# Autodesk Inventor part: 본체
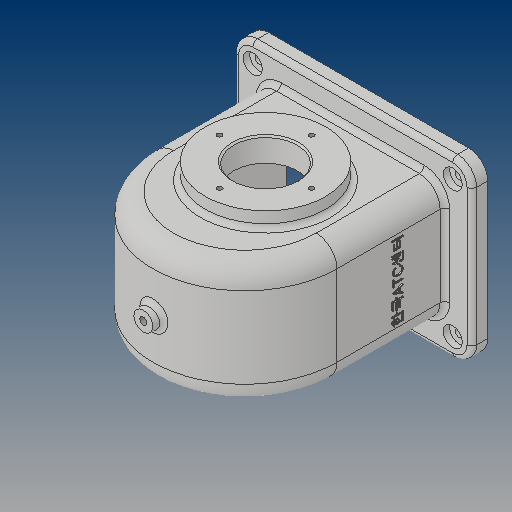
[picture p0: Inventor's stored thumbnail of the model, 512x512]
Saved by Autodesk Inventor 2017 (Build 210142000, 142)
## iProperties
Part Number: 본체
Material: 일반
Document SubType Name: Modeling
Designer: 20
Density: 1 g/cm^3
Appearance: 기본값
Mass: 404.475 g
Surface Area: 1182.21 cm^2
Volume: 404.475 cm^3
Author: 20
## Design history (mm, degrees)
sketch "스케치1"
  geometry: L1 (81.2, 0)-(-81.2, 0) reference; L2 (0, -105.2)-(0, 85.2) reference; L3 (58, -78)-(-58, -78); L4 (58, 0)-(58, -78); L5 (-58, 0)-(-58, -78); A1 r 58 centre (0, 0) between (58, 0) and (-58, 0); 1 further point
  constraints: 6 end point, 2 point on circle, 2 point on line, 2 vertical, 1 centre point, 1 coincident, 1 parallel, 1 tangent
  dimensions: "d0" = 78 distance between parallel lines of L1 L3; "d3" = 116 diameter of A1
extrude "돌출1" new body sketch "스케치1" stored distance "d4" = 77; taper "d5" = 0 deg
sketch "스케치2"
  geometry: L1 (81.2, 0)-(-81.2, 0) reference; L2 (0, -105.2)-(0, 85.2) reference; L3 (52, 0)-(52, -78); L4 (-58, -78)-(58, -78) reference; L5 (-52, 0)-(-52, -78); L6 (-52, -78)-(52, -78); A1 r 52 centre (0, 0) between (52, 0) and (-52, 0); A2 r 58 centre (0, 0) between (58, 0) and (-58, 0) reference; 1 further point
  constraints: 6 end point, 4 point on line, 2 point on circle, 2 vertical, 1 centre point, 1 coincident, 1 horizontal, 1 tangent
  dimensions: "d6" = 6 radial gap between concentric circles of A2 A1
extrude "돌출3" cut sketch "스케치2" stored distance "d14" = 67; taper "d15" = 0 deg
node "작업 평면1"
sketch "스케치3"
  geometry: L1 (-81.2, 0)-(81.2, 0) reference; L2 (0, -53.9)-(0, 53.9) reference; L3 (-75, -55)-(75, -55); L4 (75, -55)-(75, 55); L5 (75, 55)-(-75, 55); L6 (-75, 55)-(-75, -55); L7 (52, -33.5)-(52, 33.5) reference; L8 (52, -33.5)-(-52, -33.5) reference; L9 (-52, -33.5)-(-52, 33.5) reference; L10 (-52, 33.5)-(52, 33.5) reference; 1 further point
  constraints: 8 end point, 2 parallel, 1 horizontal, 1 perpendicular
  dimensions: "d10" = 110 distance of L5.end L3.start; "d11" = 150 distance of L4.end L5.end; "d12" = 75 distance between parallel lines of L2 L6; "d13" = 55 distance between parallel lines of L1 L3
extrude "돌출4" join sketch "스케치3" distance "d16" = 10; taper "d17" = 0 deg
sketch "스케치4"
  geometry: L1 (-105, 0)-(105, 0) reference; L2 (0, -105.2)-(0, 85.2) reference; L3 (-75, -78)-(75, -78) reference; C1 r 38 at (0, -13); 1 further point
  constraints: 1 centre point, 1 point on line
  dimensions: "d18" = 65 distance from line of L3 C1.centre; "d19" = 76 diameter of C1
extrude "돌출5" join sketch "스케치4" distance "d20" = 5; taper "d21" = 0 deg
sketch "스케치5"
  geometry: L1 (-105, 0)-(105, 0) reference; L2 (0, 105.2)-(0, -85.2) reference; L3 (75, 78)-(-75, 78) reference; C1 r 38 at (0, 13); 1 further point
  constraints: 1 centre point, 1 point on line
  dimensions: "d22" = 65 distance from line of L3 C1.centre; "d23" = 76 diameter of C1
extrude "돌출6" join sketch "스케치5" distance "d24" = 10; taper "d25" = 0 deg
sketch "스케치6"
  geometry: L1 (-105, 0)-(105, 0) reference; L2 (0, 105.2)-(0, -85.2) reference; L3 (-75, 78)-(75, 78) reference; C1 r 28 at (0, 13); 1 further point
  constraints: 1 centre point, 1 point on line
  dimensions: "d26" = 65 distance from line of L3 C1.centre; "d27" = 56 diameter of C1
extrude "돌출7" join sketch "스케치6" distance "d28" = 14; taper "d29" = 0 deg
feature "면 기울기1" dims angle "d30" = 40 deg
sketch "스케치7"
  geometry: C1 r 38 at (0, 0) reference; C2 r 20 at (0, 0); 1 further point
  constraints: 1 centre point, 1 coincident
  dimensions: "d31" = 40 diameter of C2
extrude "돌출8" cut sketch "스케치7" stored distance "d32" = 14; taper "d33" = 0 deg
node "작업 평면2"
sketch "스케치8"
  geometry: L1 (0, -77)-(0, 77) reference; L2 (-105, 0)-(105, 0) reference; L3 (-75, 55)-(-75, -55) reference; C1 r 6 at (0, 0); 1 further point
  constraints: 1 centre point, 1 midpoint
  dimensions: "d35" = 75 distance from line of L3 C1.centre; "d36" = 12 diameter of C1
extrude "돌출9" join sketch "스케치8" stored distance "d37" = 14; taper "d38" = 5 deg
fillet "모깎기1" dims "d39" = 12
sketch "스케치10"
  geometry: L1 (-105, 0)-(105, 0) reference; C1 r 6 at (-63, -43); A1 r 12 centre (-63, -43) between (-75, -43) and (-63, -55) reference; 1 further point
  constraints: 1 centre point, 1 coincident
  dimensions: "d40" = 12 diameter of C1
hole "구멍1" sketch "스케치10" at (-63, -43) diameter "d41" = 5; stored, may be unused: countersink angle "d45" = 90 deg, drill point angle "d47" = 0 deg; dims "d42" = 6, "d43" = 12, "d44" = 4, "d46" = 8
sketch "스케치11" dims "d48" = 58
  geometry: L1 (-105, 13)-(105, 13) reference; L2 (0, -93.4)-(0, 105.4) reference; C1 r 38 at (0, 0) reference; C2 r 2 at (0, 29); 2 further points
  constraints: 1 centre point, 1 coincident, 1 point on line, 1 vertical alignment, 2 other
  dimensions: "d49" = 4 diameter of C2
hole "구멍2" sketch "스케치11" at (0, 29) diameter "d50" = 3.242; stored, may be unused: countersink angle "d54" = 90 deg, drill point angle "d56" = 118 deg; dims "d51" = 8, "d52" = 12, "d53" = 4, "d55" = 10
sketch "스케치12" dims "d60" = 58
  geometry: L1 (0, 93.4)-(0, -105.4) reference; C1 r 38 at (0, 0) reference; C2 r 2 at (0, -29); 2 further points
  constraints: 1 centre point, 1 coincident, 1 point on line, 1 vertical alignment, 2 other
  dimensions: "d61" = 4 diameter of C2
hole "구멍3" sketch "스케치12" at (0, -29) diameter "d62" = 3.242; stored, may be unused: countersink angle "d66" = 90 deg, drill point angle "d68" = 118 deg; dims "d63" = 8, "d64" = 12, "d65" = 4, "d67" = 10
sketch "스케치13"
  geometry: C1 r 6 at (0, 0) reference; C2 r 2.5 at (0, 0); 1 further point
  constraints: 1 centre point, 1 coincident
  dimensions: "d72" = 5 diameter of C2
hole "구멍4" sketch "스케치13" at (0, 0) diameter "d73" = 4.459; stored, may be unused: countersink angle "d77" = 90 deg, drill point angle "d79" = 0 deg; dims "d74" = 10, "d75" = 12, "d76" = 4, "d78" = 12.8
fillet "모깎기2" dims "d80" = 3
fillet "모깎기3" dims "d81" = 13
fillet "모깎기4" dims "d82" = 8
fillet "모깎기5" dims "d83" = 3
fillet "모깎기6" dims "d84" = 3
fillet "모깎기7" dims "d85" = 3
chamfer "모따기1" distance "d86" = 1; stored, may be unused: second distance "d87" = 2, angle "d88" = 45 deg
fillet "모깎기8" dims "d89" = 3
sketch "스케치14"
  geometry: L1 (78, -17.5)-(78, 68.5) reference; L2 (0, -13)-(65, -13) reference; 2 further points
  constraints: 1 other
  dimensions: "d90" = 40 distance from line of L1 point (38, 25.5); "d91" = 38.5 distance from line of L2 point (38, 25.5)
feature "엠보싱1" sketch "스케치14" dims "d92" = 0.5, "d93" = 0
node "솔리드1"
mirror "미러1"
mirror "미러2"
pattern_circular "원형 패턴1" dims angle "d58" = 360 deg
pattern_circular "원형 패턴2" dims angle "d70" = 360 deg
node "투영된 루프1"
other parameters: "d9" = -78, "d34" = 142
